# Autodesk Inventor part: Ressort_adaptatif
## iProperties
Shininess: 64.0
Length Units: 11269
Angle Units: 11279
Time Units: 11290
Mass Units: 11283
Length Display Precision: 3
Angle Display Precision: 2
Compacted: True
Part Number: Ressort_adaptatif
Document SubType Name: Modeling
Created: 2004-04
Material: Par défaut
Designer: flavienm
Density: 0.0
Volumn: 0.0
Area: 0.0
PropertySet Name: Model Information
Control State: 0
Master: False
Checked Out: False
Author: flavienm
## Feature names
1. Hélicoïde1
